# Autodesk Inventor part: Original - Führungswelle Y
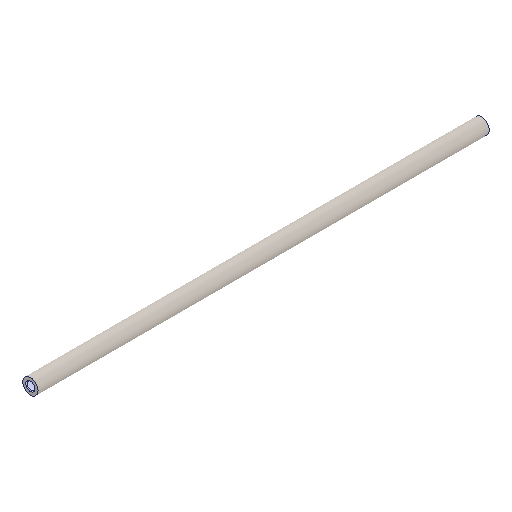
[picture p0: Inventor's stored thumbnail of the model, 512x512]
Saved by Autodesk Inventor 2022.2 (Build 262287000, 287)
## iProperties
Created: 2024-09
Part Number: Original - Führungswelle Y
Material: Generico
Document SubType Name: Modeling
Designer: 18907419
Density: 1 g/cm^3
Appearance: Default
Author: 18907419
Revision Number: ANY
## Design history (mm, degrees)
feature "Fase1"
node "Solido1"
